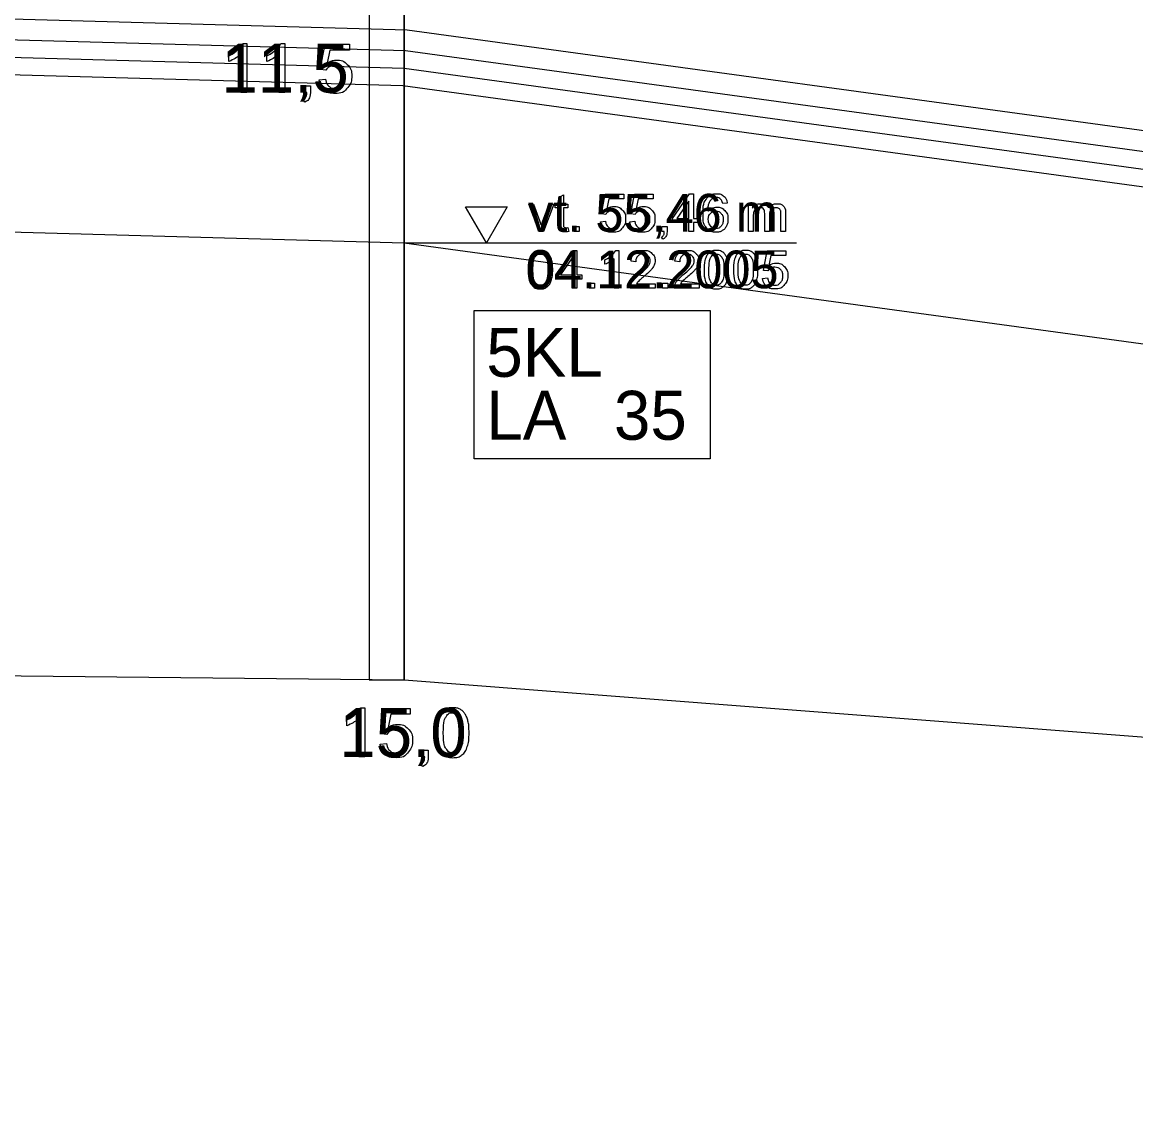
# Model space of a CAD drawing. Extents: x 532503 to 539665, y 6557663 to 6561526.
# Drawn here: x 538113.6 to 538241, y 6560172.1 to 6560296.3 of the extents above; entities that cross this region are included whole.
import ezdxf

# ---------------------------------------------------------------- set-up
doc = ezdxf.new("R2010")
doc.units = 0
for name, color, linetype in [('GEOLPUNKT', 7, 'Continuous'), ('illumineerimisjooned', 7, 'Continuous'), ('Kaitsevöönd', 7, 'Continuous'), ('PIIR', 7, 'Continuous'), ('Plokid', 7, 'Continuous'), ('Proovid', 7, 'Continuous'), ('Täide', 7, 'Continuous'), ('Veetase', 7, 'Continuous'), ('VORMISTUS', 7, 'Continuous')]:
    doc.layers.add(name, color=color, linetype=linetype)

msp = doc.modelspace()

# ---------------------------------------------------------------- linework, layer by layer
at = {"layer": 'GEOLPUNKT'}
msp.add_line((538157.31, 6560521.07), (538157.31, 6560221.07), dxfattribs=at)
for points in [[(538152.35, 6560217.89), (538152.8, 6560217.89), (538152.8, 6560212.27)], [(538155.33, 6560214.84), (538154.68, 6560214.92), (538155.23, 6560217.8), (538158.01, 6560217.8), (538158.01, 6560217.14), (538155.78, 6560217.14), (538155.47, 6560215.64)], [(538150.74, 6560215.82), (538150.74, 6560216.49)], [(538152.8, 6560212.27), (538152.11, 6560212.27), (538152.11, 6560216.65)], [(538154.56, 6560213.74), (538155.28, 6560213.8)], [(538159.28, 6560212.27), (538159.28, 6560213.05), (538160.06, 6560213.05), (538160.06, 6560212.27)], [(538159.67, 6560212.27), (538159.28, 6560212.27)], [(538159.43, 6560211.16), (538159.23, 6560211.45)]]:
    msp.add_lwpolyline(points, dxfattribs=at)
for points in [[(538150.74, 6560216.49), (538151.31, 6560216.76), (538151.74, 6560217.14), (538152.18, 6560217.53), (538152.35, 6560217.89)], [(538161.08, 6560215.03), (538161.08, 6560216.02), (538161.29, 6560216.63), (538161.49, 6560217.24), (538161.89, 6560217.56), (538162.3, 6560217.89), (538162.91, 6560217.89), (538163.36, 6560217.89), (538163.7, 6560217.71), (538164.04, 6560217.53), (538164.26, 6560217.19), (538164.48, 6560216.85), (538164.61, 6560216.35), (538164.73, 6560215.86), (538164.73, 6560215.03), (538164.73, 6560214.05), (538164.53, 6560213.44), (538164.33, 6560212.83), (538163.92, 6560212.51), (538163.52, 6560212.18), (538162.91, 6560212.18), (538162.1, 6560212.18), (538161.64, 6560212.75), (538161.08, 6560213.46), (538161.08, 6560215.03)], [(538161.79, 6560215.03), (538161.79, 6560213.65), (538162.11, 6560213.2), (538162.43, 6560212.74), (538162.91, 6560212.74), (538163.38, 6560212.74), (538163.7, 6560213.2), (538164.02, 6560213.65), (538164.02, 6560215.03), (538164.02, 6560216.41), (538163.7, 6560216.87), (538163.38, 6560217.32), (538162.9, 6560217.32), (538162.43, 6560217.32), (538162.14, 6560216.92), (538161.79, 6560216.41), (538161.79, 6560215.03)], [(538152.11, 6560216.65), (538151.86, 6560216.41), (538151.46, 6560216.18), (538151.06, 6560215.94), (538150.74, 6560215.82)], [(538155.47, 6560215.64), (538155.98, 6560215.99), (538156.53, 6560215.99), (538157.27, 6560215.99), (538157.77, 6560215.48), (538158.27, 6560214.97), (538158.27, 6560214.17), (538158.27, 6560213.41), (538157.83, 6560212.86), (538157.29, 6560212.18), (538156.36, 6560212.18), (538155.6, 6560212.18), (538155.11, 6560212.6), (538154.63, 6560213.03), (538154.56, 6560213.74)], [(538155.28, 6560213.8), (538155.36, 6560213.27), (538155.65, 6560213.01), (538155.94, 6560212.74), (538156.36, 6560212.74), (538156.86, 6560212.74), (538157.2, 6560213.11), (538157.54, 6560213.49), (538157.54, 6560214.11), (538157.54, 6560214.7), (538157.22, 6560215.04), (538156.89, 6560215.38), (538156.35, 6560215.38), (538156.01, 6560215.38), (538155.75, 6560215.23), (538155.48, 6560215.08), (538155.33, 6560214.84)], [(538159.23, 6560211.45), (538159.45, 6560211.55), (538159.56, 6560211.74), (538159.66, 6560211.92), (538159.67, 6560212.27)], [(538160.06, 6560212.27), (538160.06, 6560211.84), (538159.91, 6560211.57), (538159.76, 6560211.31), (538159.43, 6560211.16)]]:
    msp.add_open_spline(points, degree=3, dxfattribs=at)
at = {"layer": 'illumineerimisjooned'}
msp.add_lwpolyline([(537116.81, 6560201.03), (537409.75, 6560249.66), (537680.21, 6560267.06), (537927.18, 6560299.47), (538157.47, 6560293.07), (538426.89, 6560256.25), (538557.08, 6560232.84), (538708.68, 6560211.09)], dxfattribs=at)
at = {"layer": 'Kaitsevöönd'}
msp.add_lwpolyline([(537081.83, 6560005.9), (537114.82, 6560006.67), (537183.93, 6560026.73), (537280.03, 6560100.21), (537353.48, 6560157.72), (537409.98, 6560181.67), (537680.4, 6560181.07), (537927.28, 6560223.47), (538157.31, 6560221.07), (538426.58, 6560200.27), (538783.9, 6560154.27), (538809.14, 6560154.38)], dxfattribs=at)
at = {"layer": 'PIIR'}
msp.add_lwpolyline([(537114.81, 6560198.67), (537409.98, 6560247.67), (537680.4, 6560265.07), (537927.28, 6560297.47), (538157.31, 6560291.07), (538426.58, 6560254.27), (538556.76, 6560230.87), (538710.68, 6560208.78)], dxfattribs=at)
at = {"layer": 'Plokid'}
for points in [[(537119.21, 6560203.86), (537409.48, 6560252.05), (537679.98, 6560269.45), (537927.05, 6560301.88), (538157.67, 6560295.46), (538427.26, 6560258.62), (538557.47, 6560235.21), (538706.28, 6560213.86)], [(537119.21, 6560197.37), (537410.21, 6560245.68), (537680.6, 6560263.08), (537927.38, 6560295.47), (538157.15, 6560289.07), (538426.26, 6560252.29), (538556.44, 6560228.9), (538710.39, 6560206.8)]]:
    msp.add_lwpolyline(points, dxfattribs=at)
at = {"layer": 'Proovid'}
for points in [[(538157.31, 6560301.07), (538153.31, 6560301.07), (538153.31, 6560221.07), (538157.31, 6560221.07)], [(538165.31, 6560263.35), (538192.31, 6560263.35), (538192.31, 6560246.35), (538165.31, 6560246.35)]]:
    msp.add_lwpolyline(points, close=True, dxfattribs=at)
for points in [[(538138.87, 6560293.89), (538139.31, 6560293.89), (538139.31, 6560288.27)], [(538143.22, 6560293.89), (538143.66, 6560293.89), (538143.66, 6560288.27)], [(538148.36, 6560290.84), (538147.72, 6560290.92), (538148.26, 6560293.8), (538151.04, 6560293.8), (538151.04, 6560293.14), (538148.81, 6560293.14), (538148.51, 6560291.64)], [(538137.25, 6560291.82), (538137.25, 6560292.49)], [(538139.31, 6560288.27), (538138.62, 6560288.27), (538138.62, 6560292.65)], [(538141.6, 6560291.82), (538141.6, 6560292.49)], [(538143.66, 6560288.27), (538142.97, 6560288.27), (538142.97, 6560292.65)], [(538147.6, 6560289.74), (538148.32, 6560289.8)], [(538145.79, 6560288.27), (538145.79, 6560289.05), (538146.58, 6560289.05), (538146.58, 6560288.27)], [(538146.18, 6560288.27), (538145.79, 6560288.27)], [(538145.94, 6560287.16), (538145.75, 6560287.45)]]:
    msp.add_lwpolyline(points, dxfattribs=at)
for points in [[(538137.25, 6560292.49), (538137.83, 6560292.76), (538138.26, 6560293.14), (538138.69, 6560293.53), (538138.87, 6560293.89)], [(538141.6, 6560292.49), (538142.18, 6560292.76), (538142.61, 6560293.14), (538143.04, 6560293.53), (538143.22, 6560293.89)], [(538138.62, 6560292.65), (538138.38, 6560292.41), (538137.97, 6560292.18), (538137.57, 6560291.94), (538137.25, 6560291.82)], [(538142.97, 6560292.65), (538142.73, 6560292.41), (538142.32, 6560292.18), (538141.92, 6560291.94), (538141.6, 6560291.82)], [(538148.51, 6560291.64), (538149.01, 6560291.99), (538149.57, 6560291.99), (538150.3, 6560291.99), (538150.81, 6560291.48), (538151.31, 6560290.97), (538151.31, 6560290.17), (538151.31, 6560289.41), (538150.87, 6560288.86), (538150.33, 6560288.18), (538149.4, 6560288.18), (538148.63, 6560288.18), (538148.15, 6560288.6), (538147.66, 6560289.03), (538147.6, 6560289.74)], [(538148.32, 6560289.8), (538148.4, 6560289.27), (538148.69, 6560289.01), (538148.98, 6560288.74), (538149.39, 6560288.74), (538149.89, 6560288.74), (538150.24, 6560289.11), (538150.58, 6560289.49), (538150.58, 6560290.11), (538150.58, 6560290.7), (538150.25, 6560291.04), (538149.92, 6560291.38), (538149.38, 6560291.38), (538149.05, 6560291.38), (538148.78, 6560291.23), (538148.52, 6560291.08), (538148.36, 6560290.84)], [(538145.75, 6560287.45), (538145.97, 6560287.55), (538146.07, 6560287.74), (538146.17, 6560287.92), (538146.18, 6560288.27)], [(538146.58, 6560288.27), (538146.58, 6560287.84), (538146.42, 6560287.57), (538146.27, 6560287.31), (538145.94, 6560287.16)]]:
    msp.add_open_spline(points, degree=3, dxfattribs=at)
at = {"layer": 'Täide'}
for points in [[(537822.21, 6560205.42), (537927.28, 6560223.47), (538157.31, 6560221.07), (538426.58, 6560200.27), (538783.9, 6560154.27), (538809.14, 6560154.38)], [(537927.28, 6560223.47), (538157.31, 6560221.07), (538426.58, 6560200.27), (538783.9, 6560154.27)]]:
    msp.add_lwpolyline(points, dxfattribs=at)
at = {"layer": 'Veetase'}
msp.add_lwpolyline([(537081.83, 6560175.11), (537114.82, 6560178.67), (537409.98, 6560227.67), (537680.4, 6560245.07), (537927.28, 6560277.47), (538157.31, 6560271.07), (538426.58, 6560234.27), (538783.9, 6560178.27), (538809.14, 6560175.71)], dxfattribs=at)
at = {"layer": 'VORMISTUS'}
msp.add_line((538157.31, 6560271.07), (538202.18, 6560271.07), dxfattribs=at)
for points in [[(538189.86, 6560272.36), (538189.86, 6560273.4), (538187.99, 6560273.4), (538187.99, 6560273.88), (538189.96, 6560276.68), (538190.39, 6560276.68), (538190.39, 6560273.88), (538190.98, 6560273.88), (538190.98, 6560273.4), (538190.39, 6560273.4), (538190.39, 6560272.36), (538189.86, 6560272.36)], [(538172.74, 6560272.36), (538171.56, 6560275.49), (538172.12, 6560275.49), (538172.79, 6560273.62)], [(538173.18, 6560273.58), (538173.88, 6560275.49), (538174.42, 6560275.49), (538173.24, 6560272.36), (538172.74, 6560272.36)], [(538174.99, 6560273.28), (538174.99, 6560275.08), (538174.6, 6560275.08), (538174.6, 6560275.49), (538174.99, 6560275.49), (538174.99, 6560276.27), (538175.52, 6560276.59), (538175.52, 6560275.49), (538176.05, 6560275.49), (538176.05, 6560275.08), (538175.52, 6560275.08), (538175.52, 6560273.25)], [(538180.37, 6560274.34), (538179.87, 6560274.41), (538180.29, 6560276.63), (538182.44, 6560276.63), (538182.44, 6560276.12), (538180.71, 6560276.12), (538180.48, 6560274.96)], [(538183.72, 6560274.34), (538183.23, 6560274.41), (538183.65, 6560276.63), (538185.79, 6560276.63), (538185.79, 6560276.12), (538184.07, 6560276.12), (538183.84, 6560274.96)], [(538189.86, 6560273.88), (538189.86, 6560275.83), (538188.51, 6560273.88), (538189.86, 6560273.88)], [(538194.27, 6560275.62), (538193.75, 6560275.58)], [(538196.7, 6560272.36), (538196.7, 6560275.49), (538197.17, 6560275.49), (538197.17, 6560275.05)], [(538199.09, 6560274.18), (538199.09, 6560272.36), (538198.56, 6560272.36), (538198.56, 6560274.39)], [(538200.94, 6560274.51), (538200.94, 6560272.36), (538200.41, 6560272.36), (538200.41, 6560274.33)], [(538176.05, 6560272.83), (538176.13, 6560272.37)], [(538176.72, 6560272.36), (538176.72, 6560272.96), (538177.32, 6560272.96), (538177.32, 6560272.36), (538176.72, 6560272.36)], [(538179.78, 6560273.49), (538180.33, 6560273.54)], [(538183.13, 6560273.49), (538183.69, 6560273.54)], [(538186.77, 6560272.36), (538186.77, 6560272.96), (538187.38, 6560272.96), (538187.38, 6560272.36)], [(538197.23, 6560273.98), (538197.23, 6560272.36), (538196.7, 6560272.36)], [(538186.89, 6560271.51), (538186.74, 6560271.73)], [(538187.07, 6560272.36), (538186.77, 6560272.36)], [(538176.54, 6560265.88), (538176.54, 6560266.92), (538174.67, 6560266.92), (538174.67, 6560267.4), (538176.63, 6560270.2), (538177.07, 6560270.2), (538177.07, 6560267.4), (538177.65, 6560267.4), (538177.65, 6560266.92), (538177.07, 6560266.92), (538177.07, 6560265.88), (538176.54, 6560265.88)], [(538176.54, 6560267.4), (538176.54, 6560269.35), (538175.19, 6560267.4), (538176.54, 6560267.4)], [(538180.28, 6560268.62), (538180.28, 6560269.13)], [(538181.87, 6560265.88), (538181.34, 6560265.88), (538181.34, 6560269.26)], [(538181.52, 6560270.22), (538181.87, 6560270.22), (538181.87, 6560265.88)], [(538198.92, 6560267.86), (538198.42, 6560267.93), (538198.84, 6560270.15), (538200.98, 6560270.15), (538200.98, 6560269.64), (538199.26, 6560269.64), (538199.03, 6560268.48)], [(538183.8, 6560268.91), (538183.26, 6560268.97)], [(538188.83, 6560268.91), (538188.29, 6560268.97)], [(538178.49, 6560265.88), (538178.49, 6560266.48), (538179.09, 6560266.48), (538179.09, 6560265.88), (538178.49, 6560265.88)], [(538186.88, 6560265.88), (538186.88, 6560266.48), (538187.48, 6560266.48), (538187.48, 6560265.88), (538186.88, 6560265.88)], [(538198.32, 6560267.01), (538198.88, 6560267.06)], [(538186.01, 6560266.39), (538186.01, 6560265.88), (538183.16, 6560265.88)], [(538183.89, 6560266.39), (538186.01, 6560266.39)], [(538191.04, 6560266.39), (538191.04, 6560265.88), (538188.19, 6560265.88)], [(538188.93, 6560266.39), (538191.04, 6560266.39)]]:
    msp.add_lwpolyline(points, dxfattribs=at)
msp.add_lwpolyline([(538166.72, 6560275.21), (538169.11, 6560275.21), (538166.72, 6560271.07), (538164.34, 6560275.21)], close=True, dxfattribs=at)
for points in [[(538193.75, 6560275.58), (538193.68, 6560275.89), (538193.55, 6560276.03), (538193.33, 6560276.26), (538193.02, 6560276.26), (538192.76, 6560276.26), (538192.57, 6560276.12), (538192.32, 6560275.94), (538192.17, 6560275.59), (538192.03, 6560275.24), (538192.02, 6560274.59), (538192.21, 6560274.88), (538192.49, 6560275.02), (538192.77, 6560275.16), (538193.07, 6560275.16), (538193.6, 6560275.16), (538193.98, 6560274.77), (538194.35, 6560274.38), (538194.35, 6560273.76), (538194.35, 6560273.36), (538194.17, 6560273.01), (538194, 6560272.66), (538193.69, 6560272.47), (538193.39, 6560272.29), (538193, 6560272.29), (538192.33, 6560272.29), (538191.91, 6560272.78), (538191.5, 6560273.26), (538191.5, 6560274.38), (538191.5, 6560275.63), (538191.96, 6560276.2), (538192.36, 6560276.7), (538193.05, 6560276.7), (538193.56, 6560276.7), (538193.88, 6560276.41), (538194.21, 6560276.13), (538194.27, 6560275.62)], [(538197.17, 6560275.05), (538197.32, 6560275.28), (538197.56, 6560275.42), (538197.81, 6560275.56), (538198.12, 6560275.56), (538198.47, 6560275.56), (538198.69, 6560275.42), (538198.91, 6560275.27), (538199.01, 6560275.01), (538199.38, 6560275.56), (538199.97, 6560275.56), (538200.44, 6560275.56), (538200.69, 6560275.3), (538200.94, 6560275.05), (538200.94, 6560274.51)], [(538180.48, 6560274.96), (538180.87, 6560275.23), (538181.3, 6560275.23), (538181.86, 6560275.23), (538182.25, 6560274.84), (538182.64, 6560274.44), (538182.64, 6560273.83), (538182.64, 6560273.24), (538182.3, 6560272.81), (538181.88, 6560272.29), (538181.17, 6560272.29), (538180.58, 6560272.29), (538180.2, 6560272.62), (538179.83, 6560272.95), (538179.78, 6560273.49)], [(538180.33, 6560273.54), (538180.4, 6560273.13), (538180.62, 6560272.93), (538180.84, 6560272.72), (538181.16, 6560272.72), (538181.55, 6560272.72), (538181.81, 6560273.01), (538182.08, 6560273.3), (538182.08, 6560273.78), (538182.08, 6560274.24), (538181.82, 6560274.5), (538181.57, 6560274.76), (538181.16, 6560274.76), (538180.9, 6560274.76), (538180.69, 6560274.64), (538180.49, 6560274.53), (538180.37, 6560274.34)], [(538183.84, 6560274.96), (538184.23, 6560275.23), (538184.65, 6560275.23), (538185.22, 6560275.23), (538185.61, 6560274.84), (538186, 6560274.44), (538186, 6560273.83), (538186, 6560273.24), (538185.66, 6560272.81), (538185.24, 6560272.29), (538184.52, 6560272.29), (538183.93, 6560272.29), (538183.56, 6560272.62), (538183.19, 6560272.95), (538183.13, 6560273.49)], [(538183.69, 6560273.54), (538183.75, 6560273.13), (538183.98, 6560272.93), (538184.2, 6560272.72), (538184.52, 6560272.72), (538184.91, 6560272.72), (538185.17, 6560273.01), (538185.43, 6560273.3), (538185.43, 6560273.78), (538185.43, 6560274.24), (538185.18, 6560274.5), (538184.93, 6560274.76), (538184.51, 6560274.76), (538184.25, 6560274.76), (538184.05, 6560274.64), (538183.84, 6560274.53), (538183.72, 6560274.34)], [(538192.1, 6560273.76), (538192.1, 6560273.49), (538192.22, 6560273.24), (538192.34, 6560272.99), (538192.55, 6560272.85), (538192.75, 6560272.72), (538192.99, 6560272.72), (538193.32, 6560272.72), (538193.56, 6560272.99), (538193.8, 6560273.27), (538193.8, 6560273.73), (538193.8, 6560274.18), (538193.57, 6560274.44), (538193.33, 6560274.7), (538192.96, 6560274.7), (538192.61, 6560274.7), (538192.36, 6560274.44), (538192.1, 6560274.18), (538192.1, 6560273.76)], [(538198.56, 6560274.39), (538198.56, 6560274.75), (538198.43, 6560274.92), (538198.3, 6560275.1), (538198, 6560275.1), (538197.78, 6560275.1), (538197.59, 6560274.98), (538197.4, 6560274.87), (538197.31, 6560274.64), (538197.23, 6560274.41), (538197.23, 6560273.98)], [(538200.41, 6560274.33), (538200.41, 6560274.65), (538200.36, 6560274.79), (538200.31, 6560274.93), (538200.17, 6560275.02), (538200.04, 6560275.1), (538199.85, 6560275.1), (538199.52, 6560275.1), (538199.31, 6560274.88), (538199.09, 6560274.66), (538199.09, 6560274.18)], [(538172.79, 6560273.62), (538172.89, 6560273.31), (538172.99, 6560272.99), (538173.06, 6560273.23), (538173.18, 6560273.58)], [(538176.13, 6560272.37), (538175.91, 6560272.32), (538175.73, 6560272.32), (538175.44, 6560272.32), (538175.28, 6560272.41), (538175.12, 6560272.5), (538175.06, 6560272.65), (538174.99, 6560272.8), (538174.99, 6560273.28)], [(538175.52, 6560273.25), (538175.52, 6560273.02), (538175.55, 6560272.95), (538175.58, 6560272.89), (538175.64, 6560272.85), (538175.7, 6560272.81), (538175.82, 6560272.81), (538175.91, 6560272.81), (538176.05, 6560272.83)], [(538186.74, 6560271.73), (538186.91, 6560271.81), (538186.99, 6560271.95), (538187.06, 6560272.09), (538187.07, 6560272.36)], [(538187.38, 6560272.36), (538187.38, 6560272.03), (538187.26, 6560271.82), (538187.14, 6560271.62), (538186.89, 6560271.51)], [(538171.48, 6560268.01), (538171.48, 6560268.78), (538171.64, 6560269.25), (538171.8, 6560269.71), (538172.11, 6560269.97), (538172.42, 6560270.22), (538172.89, 6560270.22), (538173.24, 6560270.22), (538173.5, 6560270.08), (538173.77, 6560269.94), (538173.94, 6560269.67), (538174.11, 6560269.41), (538174.2, 6560269.03), (538174.3, 6560268.65), (538174.3, 6560268.01), (538174.3, 6560267.25), (538174.14, 6560266.78), (538173.99, 6560266.32), (538173.68, 6560266.06), (538173.37, 6560265.81), (538172.89, 6560265.81), (538172.27, 6560265.81), (538171.91, 6560266.25), (538171.48, 6560266.8), (538171.48, 6560268.01)], [(538172.03, 6560268.01), (538172.03, 6560266.95), (538172.28, 6560266.59), (538172.53, 6560266.24), (538172.89, 6560266.24), (538173.26, 6560266.24), (538173.5, 6560266.6), (538173.75, 6560266.95), (538173.75, 6560268.01), (538173.75, 6560269.08), (538173.51, 6560269.43), (538173.26, 6560269.78), (538172.89, 6560269.78), (538172.52, 6560269.78), (538172.3, 6560269.47), (538172.03, 6560269.08), (538172.03, 6560268.01)], [(538180.28, 6560269.13), (538180.72, 6560269.34), (538181.05, 6560269.64), (538181.39, 6560269.94), (538181.52, 6560270.22)], [(538181.34, 6560269.26), (538181.14, 6560269.08), (538180.83, 6560268.89), (538180.52, 6560268.71), (538180.28, 6560268.62)], [(538183.16, 6560265.88), (538183.15, 6560266.07), (538183.22, 6560266.25), (538183.33, 6560266.54), (538183.57, 6560266.82), (538183.81, 6560267.11), (538184.26, 6560267.48), (538184.97, 6560268.06), (538185.21, 6560268.39), (538185.46, 6560268.73), (538185.46, 6560269.03), (538185.46, 6560269.35), (538185.23, 6560269.56), (538185.01, 6560269.78), (538184.65, 6560269.78), (538184.26, 6560269.78), (538184.03, 6560269.55), (538183.81, 6560269.32), (538183.8, 6560268.91)], [(538183.26, 6560268.97), (538183.31, 6560269.58), (538183.68, 6560269.9), (538184.04, 6560270.22), (538184.66, 6560270.22), (538185.28, 6560270.22), (538185.64, 6560269.87), (538186.01, 6560269.53), (538186.01, 6560269.02), (538186.01, 6560268.76), (538185.9, 6560268.51), (538185.79, 6560268.26), (538185.55, 6560267.98), (538185.3, 6560267.71), (538184.73, 6560267.22), (538184.25, 6560266.82), (538184.12, 6560266.68), (538183.98, 6560266.54), (538183.89, 6560266.39)], [(538188.19, 6560265.88), (538188.18, 6560266.07), (538188.25, 6560266.25), (538188.36, 6560266.54), (538188.6, 6560266.82), (538188.84, 6560267.11), (538189.29, 6560267.48), (538190, 6560268.06), (538190.24, 6560268.39), (538190.49, 6560268.73), (538190.49, 6560269.03), (538190.49, 6560269.35), (538190.26, 6560269.56), (538190.04, 6560269.78), (538189.68, 6560269.78), (538189.3, 6560269.78), (538189.07, 6560269.55), (538188.84, 6560269.32), (538188.83, 6560268.91)], [(538188.29, 6560268.97), (538188.34, 6560269.58), (538188.71, 6560269.9), (538189.07, 6560270.22), (538189.69, 6560270.22), (538190.31, 6560270.22), (538190.67, 6560269.87), (538191.04, 6560269.53), (538191.04, 6560269.02), (538191.04, 6560268.76), (538190.93, 6560268.51), (538190.82, 6560268.26), (538190.58, 6560267.98), (538190.33, 6560267.71), (538189.76, 6560267.22), (538189.28, 6560266.82), (538189.15, 6560266.68), (538189.01, 6560266.54), (538188.93, 6560266.39)], [(538191.61, 6560268.01), (538191.61, 6560268.78), (538191.77, 6560269.25), (538191.93, 6560269.71), (538192.24, 6560269.97), (538192.55, 6560270.22), (538193.02, 6560270.22), (538193.37, 6560270.22), (538193.63, 6560270.08), (538193.89, 6560269.94), (538194.06, 6560269.67), (538194.23, 6560269.41), (538194.33, 6560269.03), (538194.43, 6560268.65), (538194.43, 6560268.01), (538194.43, 6560267.25), (538194.27, 6560266.78), (538194.12, 6560266.32), (538193.81, 6560266.06), (538193.49, 6560265.81), (538193.02, 6560265.81), (538192.4, 6560265.81), (538192.04, 6560266.25), (538191.61, 6560266.8), (538191.61, 6560268.01)], [(538192.16, 6560268.01), (538192.16, 6560266.95), (538192.41, 6560266.59), (538192.66, 6560266.24), (538193.02, 6560266.24), (538193.38, 6560266.24), (538193.63, 6560266.6), (538193.88, 6560266.95), (538193.88, 6560268.01), (538193.88, 6560269.08), (538193.63, 6560269.43), (538193.39, 6560269.78), (538193.01, 6560269.78), (538192.65, 6560269.78), (538192.43, 6560269.47), (538192.16, 6560269.08), (538192.16, 6560268.01)], [(538194.97, 6560268.01), (538194.97, 6560268.78), (538195.13, 6560269.25), (538195.28, 6560269.71), (538195.59, 6560269.97), (538195.9, 6560270.22), (538196.38, 6560270.22), (538196.72, 6560270.22), (538196.99, 6560270.08), (538197.25, 6560269.94), (538197.42, 6560269.67), (538197.59, 6560269.41), (538197.69, 6560269.03), (538197.78, 6560268.65), (538197.78, 6560268.01), (538197.78, 6560267.25), (538197.63, 6560266.78), (538197.47, 6560266.32), (538197.16, 6560266.06), (538196.85, 6560265.81), (538196.38, 6560265.81), (538195.75, 6560265.81), (538195.39, 6560266.25), (538194.97, 6560266.8), (538194.97, 6560268.01)], [(538195.51, 6560268.01), (538195.51, 6560266.95), (538195.76, 6560266.59), (538196.01, 6560266.24), (538196.38, 6560266.24), (538196.74, 6560266.24), (538196.99, 6560266.6), (538197.24, 6560266.95), (538197.24, 6560268.01), (538197.24, 6560269.08), (538196.99, 6560269.43), (538196.74, 6560269.78), (538196.37, 6560269.78), (538196.01, 6560269.78), (538195.79, 6560269.47), (538195.51, 6560269.08), (538195.51, 6560268.01)], [(538199.03, 6560268.48), (538199.42, 6560268.75), (538199.84, 6560268.75), (538200.41, 6560268.75), (538200.8, 6560268.36), (538201.19, 6560267.96), (538201.19, 6560267.35), (538201.19, 6560266.76), (538200.85, 6560266.33), (538200.43, 6560265.81), (538199.71, 6560265.81), (538199.12, 6560265.81), (538198.75, 6560266.14), (538198.38, 6560266.47), (538198.32, 6560267.01)], [(538198.88, 6560267.06), (538198.94, 6560266.65), (538199.17, 6560266.45), (538199.39, 6560266.24), (538199.71, 6560266.24), (538200.1, 6560266.24), (538200.36, 6560266.53), (538200.62, 6560266.82), (538200.62, 6560267.3), (538200.62, 6560267.76), (538200.37, 6560268.02), (538200.12, 6560268.28), (538199.7, 6560268.28), (538199.44, 6560268.28), (538199.24, 6560268.16), (538199.03, 6560268.05), (538198.92, 6560267.86)]]:
    msp.add_open_spline(points, degree=3, dxfattribs=at)

# ---------------------------------------------------------------- texts
at = {"layer": 'GEOLPUNKT'}
msp.add_text('15,0', height=5.6, dxfattribs=at).set_placement((538149.89, 6560212.27))
at = {"layer": 'Proovid'}
for s, p in [('11,5', (538136.4, 6560288.27)), ('5KL', (538166.71, 6560255.75)), ('LA', (538166.71, 6560248.55)), ('35', (538181.31, 6560248.55))]:
    msp.add_text(s, height=5.6, dxfattribs=at).set_placement(p)
at = {"layer": 'VORMISTUS'}
for s, p in [('vt. 55,46 m', (538171.48, 6560272.36)), ('04.12.2005', (538171.23, 6560265.88))]:
    msp.add_text(s, height=4.32, dxfattribs=at).set_placement(p)

doc.saveas('drawing.dxf')
